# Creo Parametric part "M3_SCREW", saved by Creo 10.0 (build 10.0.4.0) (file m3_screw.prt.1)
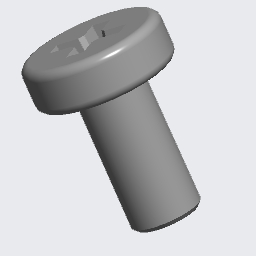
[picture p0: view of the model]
Units: millimeter Kilogram Sec (mmKs); MM, KILOGRAM, SECS

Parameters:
  PLACEMENT = "EXTERNAL"

Other parameters: MINOR_DIAMETER, PITCH

Created from: XX_SOLID_PART_MMKS_NEW_ABS.PRT

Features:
  1. datum plane "RIGHT"
  2. datum plane "TOP"
  3. datum plane "FRONT"
  4. coordinate system
  5. revolve "Revolve 1"
  6. feature "Cosmetic Thread 1"
  7. chamfer "Chamfer 1"
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
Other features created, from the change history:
  extruded cut "Extrude 1"
  chamfer "Chamfer 2"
